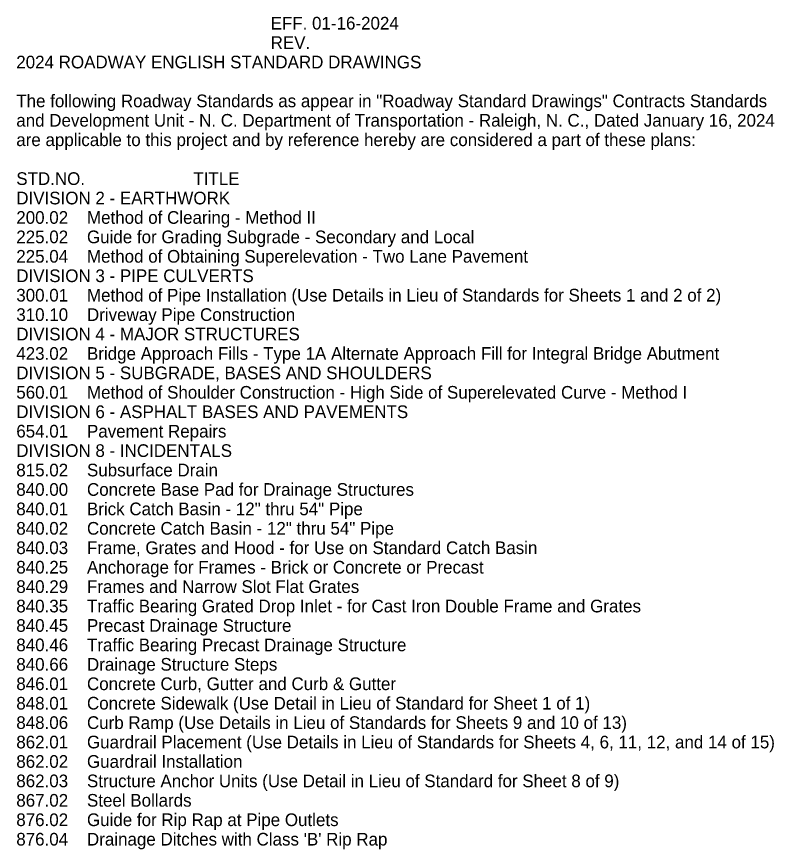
# Model space of a CAD drawing. Extents: x 1184048.9 to 1184122, y 1246638.9 to 1246660.6.
# Drawn here: x 1184048.94 to 1184057.91, y 1246649.75 to 1246659.61 of the extents above; entities that cross this region are included whole.
import ezdxf

# ---------------------------------------------------------------- set-up
doc = ezdxf.new("R2010")
doc.units = 0
doc.layers.add('Sheet Data Field CELL', color=7, linetype='Continuous')

msp = doc.modelspace()

# ---------------------------------------------------------------- texts
at = {"layer": 'Sheet Data Field CELL'}
for s, p in [('                                                      EFF. 01-16-2024', (1184048.938, 1246659.4532)), ('                                                      REV. ', (1184048.938, 1246659.2232)), ('2024 ROADWAY ENGLISH STANDARD DRAWINGS', (1184048.938, 1246658.9932)), ('The following Roadway Standards as appear in "Roadway Standard Drawings" Contracts Standards', (1184048.938, 1246658.5332)), ('and Development Unit - N. C. Department of Transportation - Raleigh, N. C., Dated January 16, 2024', (1184048.938, 1246658.3032)), ('are applicable to this project and by reference hereby are considered a part of these plans:', (1184048.938, 1246658.0732)), ('STD.NO.                       TITLE', (1184048.938, 1246657.6132)), ('DIVISION 2 - EARTHWORK', (1184048.938, 1246657.3832)), ('200.02    Method of Clearing - Method II', (1184048.938, 1246657.1532)), ('225.02    Guide for Grading Subgrade - Secondary and Local', (1184048.938, 1246656.9232)), ('225.04    Method of Obtaining Superelevation - Two Lane Pavement', (1184048.938, 1246656.6932)), ('DIVISION 3 - PIPE CULVERTS', (1184048.938, 1246656.4632)), ('300.01    Method of Pipe Installation (Use Details in Lieu of Standards for Sheets 1 and 2 of 2)', (1184048.938, 1246656.2332)), ('310.10    Driveway Pipe Construction', (1184048.938, 1246656.0032)), ('DIVISION 4 - MAJOR STRUCTURES', (1184048.938, 1246655.7732)), ('423.02    Bridge Approach Fills - Type 1A Alternate Approach Fill for Integral Bridge Abutment', (1184048.938, 1246655.5432)), ('DIVISION 5 - SUBGRADE, BASES AND SHOULDERS', (1184048.938, 1246655.3132)), ('560.01    Method of Shoulder Construction - High Side of Superelevated Curve - Method I', (1184048.938, 1246655.0832)), ('DIVISION 6 - ASPHALT BASES AND PAVEMENTS', (1184048.938, 1246654.8532)), ('654.01    Pavement Repairs', (1184048.938, 1246654.6232)), ('DIVISION 8 - INCIDENTALS', (1184048.938, 1246654.3932)), ('815.02    Subsurface Drain', (1184048.938, 1246654.1632)), ('840.00    Concrete Base Pad for Drainage Structures', (1184048.938, 1246653.9332)), ('840.01    Brick Catch Basin - 12" thru 54" Pipe', (1184048.938, 1246653.7032)), ('840.02    Concrete Catch Basin - 12" thru 54" Pipe', (1184048.938, 1246653.4732)), ('840.03    Frame, Grates and Hood - for Use on Standard Catch Basin', (1184048.938, 1246653.2432)), ('840.25    Anchorage for Frames - Brick or Concrete or Precast', (1184048.938, 1246653.0132)), ('840.29    Frames and Narrow Slot Flat Grates', (1184048.938, 1246652.7832)), ('840.35    Traffic Bearing Grated Drop Inlet - for Cast Iron Double Frame and Grates', (1184048.938, 1246652.5532)), ('840.45    Precast Drainage Structure', (1184048.938, 1246652.3232)), ('840.46    Traffic Bearing Precast Drainage Structure', (1184048.938, 1246652.0932)), ('840.66    Drainage Structure Steps', (1184048.938, 1246651.8632)), ('846.01    Concrete Curb, Gutter and Curb & Gutter', (1184048.938, 1246651.6332)), ('848.01    Concrete Sidewalk (Use Detail in Lieu of Standard for Sheet 1 of 1)', (1184048.938, 1246651.4032)), ('848.06    Curb Ramp (Use Details in Lieu of Standards for Sheets 9 and 10 of 13)', (1184048.938, 1246651.1732)), ('862.01    Guardrail Placement (Use Details in Lieu of Standards for Sheets 4, 6, 11, 12, and 14 of 15)', (1184048.938, 1246650.9432)), ('862.02    Guardrail Installation', (1184048.938, 1246650.7132)), ('862.03    Structure Anchor Units (Use Detail in Lieu of Standard for Sheet 8 of 9)', (1184048.938, 1246650.4832)), ('867.02    Steel Bollards', (1184048.938, 1246650.2532)), ('876.02    Guide for Rip Rap at Pipe Outlets', (1184048.938, 1246650.0232)), ("876.04    Drainage Ditches with Class 'B' Rip Rap", (1184048.938, 1246649.7932))]:
    msp.add_text(s, height=0.15, dxfattribs=at).set_placement(p)

doc.saveas('drawing.dxf')
